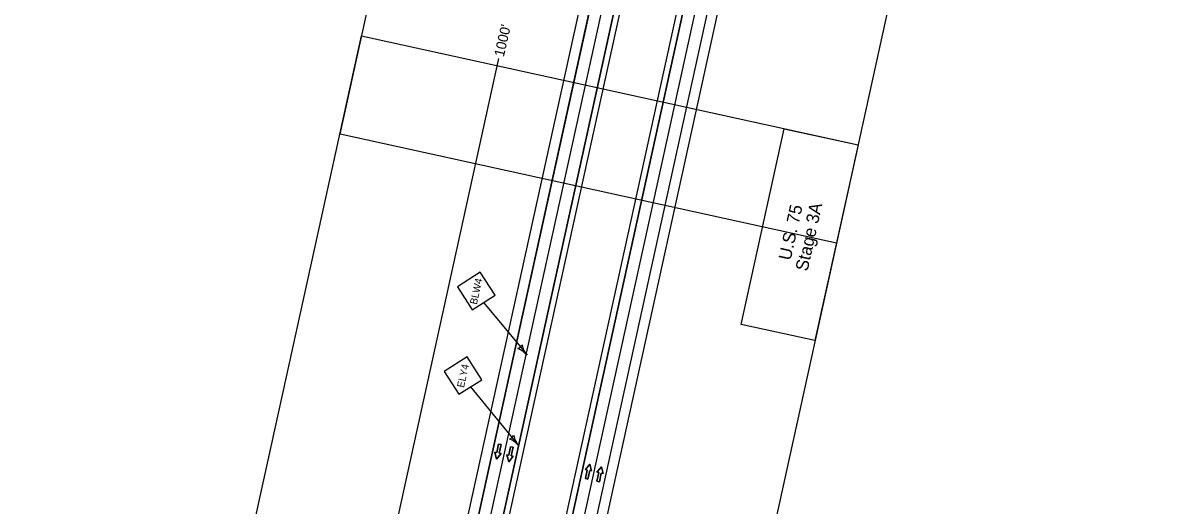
# Model space of a CAD drawing. Extents: x 14104283 to 14120882, y 8635219 to 8671666.
# Drawn here: x 14107966 to 14109111, y 8642342 to 8642822 of the extents above; entities that cross this region are included whole.
import ezdxf

# ---------------------------------------------------------------- set-up
doc = ezdxf.new("R2010")
doc.units = 0
for name, color, linetype in [('Cell', 7, 'Continuous'), ('dsnNonPlotable', 7, 'Continuous'), ('dsnPaintExistingEdgeLineRightWhite', 7, 'Continuous'), ('dsnPaintPlaceBrokenLineWhite', 7, 'Continuous'), ('dsnPaintPlaceEdgeLineLeftYellow', 7, 'Continuous'), ('dsnPaintPlaceEdgeLineRightWhite', 7, 'Continuous'), ('dsnPaintRemoveDoubleCenterLineYellow', 7, 'Continuous'), ('dsnShadingPaved', 7, 'Continuous'), ('dsnStdLabel', 7, 'Continuous'), ('dsnStgShadingPrevPav', 7, 'Continuous'), ('dsnTextOverlapEven', 7, 'Continuous')]:
    doc.layers.add(name, color=color, linetype=linetype)

msp = doc.modelspace()

# ---------------------------------------------------------------- linework, layer by layer
at = {"layer": 'Cell'}
for points in [[(14108438.8, 8642403.3), (14108441.2, 8642402.8), (14108439.4, 8642394.2), (14108441.2, 8642393.8), (14108436.8, 8642388.4), (14108435.1, 8642395.2), (14108436.9, 8642394.8)], [(14108450.7, 8642400.7), (14108453.2, 8642400.2), (14108451.3, 8642391.6), (14108453.1, 8642391.2), (14108448.8, 8642385.8), (14108447, 8642392.6), (14108448.9, 8642392.2)], [(14108527.5, 8642368.4), (14108525.1, 8642369), (14108526.9, 8642377.5), (14108525.1, 8642377.9), (14108529.5, 8642383.3), (14108531.2, 8642376.6), (14108529.4, 8642377)], [(14108538.9, 8642365.9), (14108536.5, 8642366.4), (14108538.3, 8642375), (14108536.5, 8642375.4), (14108540.9, 8642380.8), (14108542.6, 8642374.1), (14108540.8, 8642374.5)]]:
    msp.add_lwpolyline(points, close=True, dxfattribs=at)
for points in [[(14108436.9, 8642394.8), (14108435.1, 8642395.2), (14108436.8, 8642388.4), (14108441.2, 8642393.8), (14108439.4, 8642394.2), (14108441.2, 8642402.8), (14108438.8, 8642403.3), (14108436.9, 8642394.8)], [(14108448.9, 8642392.2), (14108447, 8642392.6), (14108448.8, 8642385.8), (14108453.1, 8642391.2), (14108451.3, 8642391.6), (14108453.2, 8642400.2), (14108450.7, 8642400.7), (14108448.9, 8642392.2)], [(14108529.4, 8642377), (14108531.2, 8642376.6), (14108529.5, 8642383.3), (14108525.1, 8642377.9), (14108526.9, 8642377.5), (14108525.1, 8642369), (14108527.5, 8642368.4), (14108529.4, 8642377)], [(14108540.8, 8642374.5), (14108542.6, 8642374.1), (14108540.9, 8642380.8), (14108536.5, 8642375.4), (14108538.3, 8642375), (14108536.5, 8642366.4), (14108538.9, 8642365.9), (14108540.8, 8642374.5)]]:
    msp.add_lwpolyline(points, dxfattribs=at)
at = {"layer": 'dsnNonPlotable'}
for points in [[(14108281.2, 8642711.6), (14108617.6, 8644242.5), (14109110.8, 8644134.2), (14108774.4, 8642603.2)], [(14107966.2, 8641278.2), (14108302.6, 8642809.2), (14108795.9, 8642700.9), (14108459.5, 8641169.9)]]:
    msp.add_lwpolyline(points, close=True, dxfattribs=at)
at = {"layer": 'dsnPaintExistingEdgeLineRightWhite'}
msp.add_line((14108201.6, 8640807.6), (14108724, 8643185.7), dxfattribs=at)
at = {"layer": 'dsnPaintPlaceBrokenLineWhite'}
msp.add_line((14108423.2, 8642296.7), (14108623.3, 8643207.7), dxfattribs=at)
msp.add_lwpolyline([(14108306.4, 8641340.7), (14108389, 8641717), (14108712.3, 8643188.3), (14108894.6, 8644035.3), (14109077, 8644882.2)], dxfattribs=at)
at = {"layer": 'dsnPaintPlaceEdgeLineLeftYellow'}
msp.add_line((14108199.6, 8640910.3), (14108700.5, 8643190.8), dxfattribs=at)
msp.add_lwpolyline([(14108999.8, 8644898.8), (14108635.1, 8643205.1), (14108434.9, 8642294.1)], dxfattribs=at)
at = {"layer": 'dsnPaintPlaceEdgeLineRightWhite'}
msp.add_lwpolyline([(14108976.3, 8644903.9), (14108611.6, 8643210.2), (14108202.1, 8641346.1)], dxfattribs=at)
at = {"layer": 'dsnPaintRemoveDoubleCenterLineYellow'}
msp.add_lwpolyline([(14108306.4, 8641340.7), (14108389, 8641717), (14108712.3, 8643188.3), (14108894.6, 8644035.3), (14109077, 8644882.2)], dxfattribs=at)
at = {"layer": 'dsnShadingPaved'}
for p, q in [((14108700.5, 8643190.9), (14108199.6, 8640910.3)), ((14108201.6, 8640807.6), (14108724, 8643185.7))]:
    msp.add_line(p, q, dxfattribs=at)
for points in [[(14108976.3, 8644903.9), (14108611.6, 8643210.2), (14108202.1, 8641346.1)], [(14108434.9, 8642294.1), (14108635.1, 8643205.1), (14108999.8, 8644898.8)]]:
    msp.add_lwpolyline(points, dxfattribs=at)
at = {"layer": 'dsnStdLabel'}
for p, q in [((14108438.7, 8642786.8), (14108257.8, 8641963)), ((14108423.8, 8642544.2), (14108467, 8642491.9)), ((14108410.7, 8642460.1), (14108458.6, 8642401.9))]:
    msp.add_line(p, q, dxfattribs=at)
for points in [[(14108412.4, 8642536.9), (14108435.2, 8642551.4), (14108420.6, 8642574.2), (14108397.9, 8642559.6)], [(14108399.3, 8642452.8), (14108422, 8642467.3), (14108407.5, 8642490.1), (14108384.7, 8642475.5)]]:
    msp.add_lwpolyline(points, close=True, dxfattribs=at)
for centre, radius, start, end in [((14108454.4, 8642506.5), 8.86, 292.8385, 328.307), ((14108449.5, 8642476.9), 22.9, 40.5727, 68.6439), ((14108484.4, 8642506.8), 22.9, 192.5015, 220.5728), ((14108446.1, 8642416.5), 8.86, 292.8385, 328.307), ((14108441.2, 8642387), 22.9, 40.5727, 68.6439), ((14108476.1, 8642416.9), 22.9, 192.5015, 220.5728)]:
    msp.add_arc(centre, radius, start, end, dxfattribs=at)
at = {"layer": 'dsnStgShadingPrevPav'}
for p, q in [((14108107.8, 8640963.3), (14108601.8, 8643212.3)), ((14108611.6, 8643210.2), (14108117.6, 8640961.2)), ((14108694.7, 8643192.1), (14108383, 8641773.2)), ((14108422, 8641764.6), (14108733.8, 8643183.6))]:
    msp.add_line(p, q, dxfattribs=at)
for points in [[(14108202.1, 8641346.1), (14108611.6, 8643210.2), (14108976.3, 8644903.9)], [(14108999.8, 8644898.8), (14108817.4, 8644052), (14108635.1, 8643205.1), (14108387.9, 8642080.1), (14108140.8, 8640955.1)], [(14108146.7, 8640953.8), (14108640.9, 8643203.9), (14109005.6, 8644897.6)], [(14108999.8, 8644898.8), (14108635.1, 8643205.1), (14108225.5, 8641340.9)]]:
    msp.add_lwpolyline(points, dxfattribs=at)
at = {"layer": 'dsnTextOverlapEven'}
for points in [[(14108795.9, 8642700.9), (14108753.1, 8642506.2), (14108679.8, 8642522.3), (14108722.6, 8642716.9)], [(14108679.8, 8642522.3), (14108722.6, 8642716.9), (14108795.9, 8642700.9), (14108753.1, 8642506.2)]]:
    msp.add_lwpolyline(points, close=True, dxfattribs=at)

# ---------------------------------------------------------------- texts
at = {"layer": 'dsnStdLabel'}
for s, height, rotation, p in [("1000'", 10, 77.0531, (14108443.9, 8642787.7)), ('BLW4', 7.2, 77.6078, (14108417.1, 8642541.6)), ('ELY4', 7.2, 77.6078, (14108404.3, 8642458.9))]:
    msp.add_text(s, height=height, rotation=rotation, dxfattribs=at).set_placement(p)
at = {"layer": 'dsnTextOverlapEven'}
for s, p in [('U.S. 75', (14108728.9, 8642585.3)), ('Stage 3A', (14108745.7, 8642574.5))]:
    msp.add_text(s, height=12.5, rotation=77.6078, dxfattribs=at).set_placement(p)

doc.saveas('drawing.dxf')
